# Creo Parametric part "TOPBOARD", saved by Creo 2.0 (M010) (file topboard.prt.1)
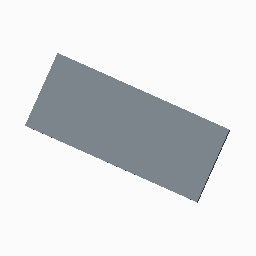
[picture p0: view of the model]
Units: Inch lbm Second (Pro/E Default); INCH, POUND, SECS

Created from: INLBS_PART_SOLID.PRT

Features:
  1. datum plane "RIGHT"
  2. datum plane "TOP"
  3. datum plane "FRONT"
  4. coordinate system
  5. sketch "Sketch 1"
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
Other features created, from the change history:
  extrusion "Extrude 1"

Surfaces: 9 plane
